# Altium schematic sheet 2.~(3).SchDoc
size 420 x 297 mm
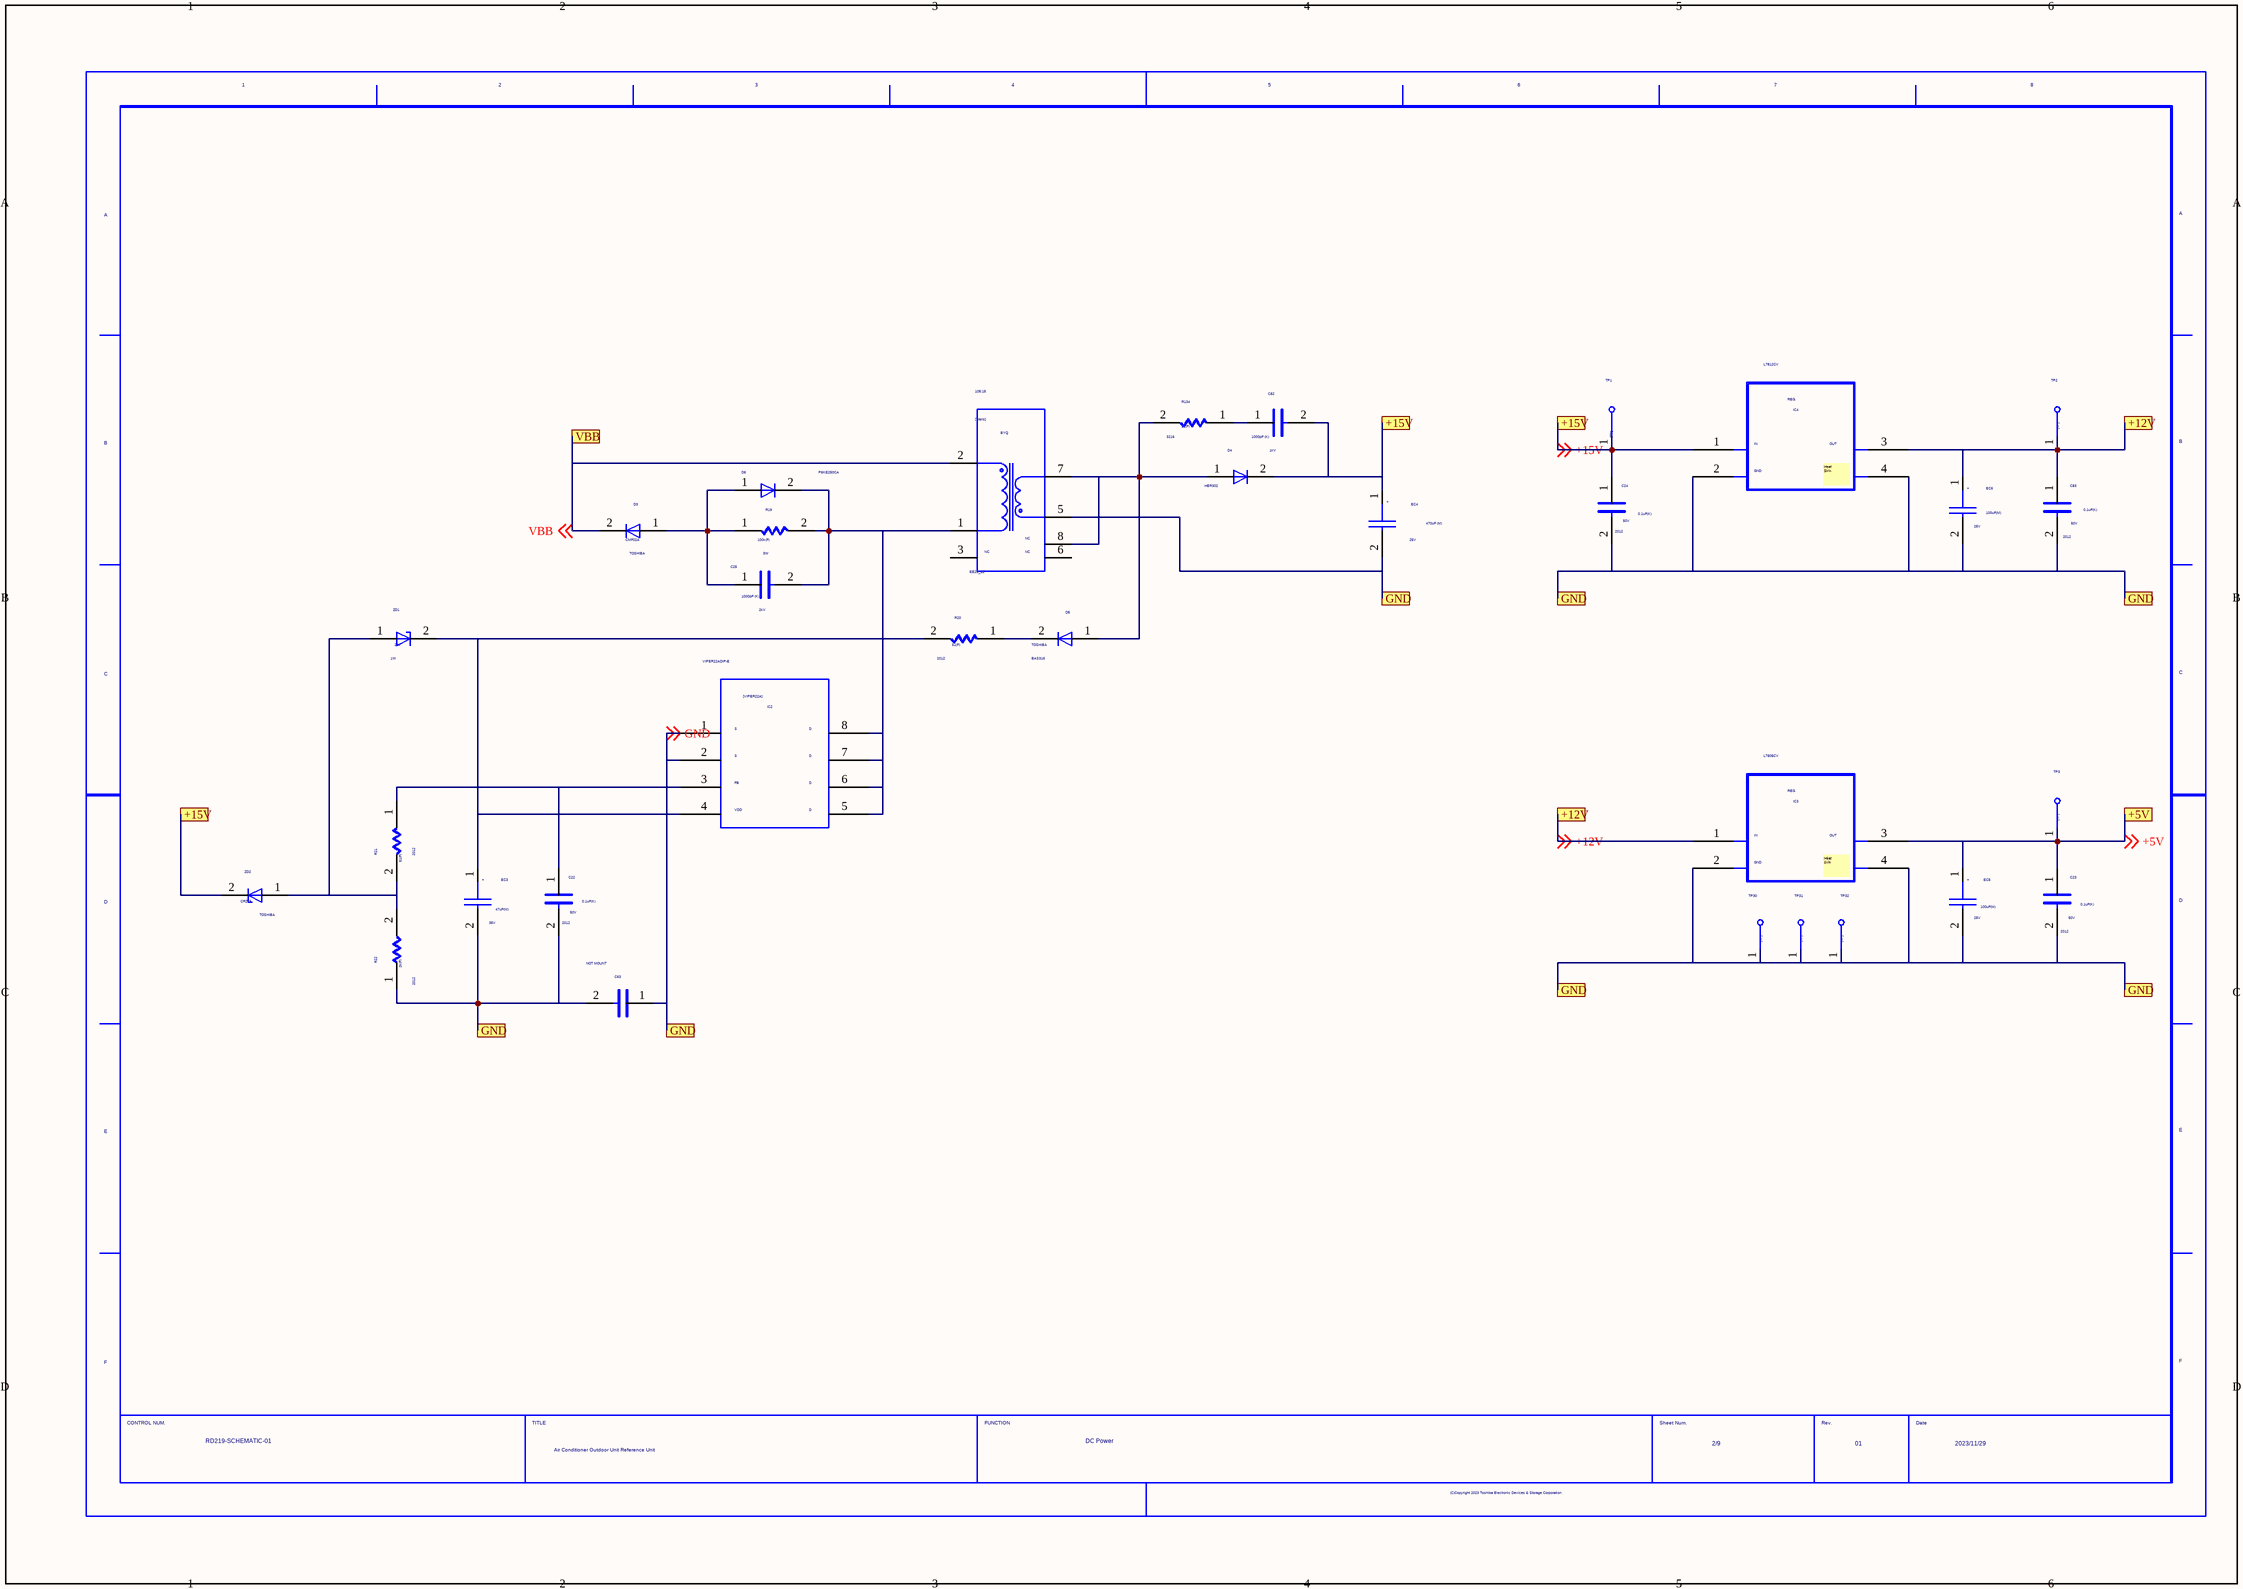
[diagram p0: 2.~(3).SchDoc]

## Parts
BYQ  VAL3: EE25_22  VAL1: 105:15  (hidden comment: EE25-22)
C22  SIZECODESMD: 2012  VAL2: 50V  VAL1: 0.1uF(K)  (hidden comment: C)
C23  SIZECODESMD: 2012  VAL2: 50V  VAL1: 0.1uF(K)  (hidden comment: C)
C24  SIZECODESMD: 2012  VAL2: 50V  VAL1: 0.1uF(K)  (hidden comment: C)
C25  VAL2: 2kV  VAL1: 1000pF (K)  (hidden comment: C)
C63  NOTMOUNT: NOT MOUNT  (hidden comment: C)
C82  VAL2: 1kV  VAL1: 1000pF (K)  (hidden comment: C)
C83  SIZECODESMD: 2012  VAL2: 50V  VAL1: 0.1uF(K)  (hidden comment: C)
D3  USERCOMPTEXT3: TOSHIBA  VAL3: CMF02A  (hidden comment: D_CUSTOM)
D4  VAL3: HER302  (hidden comment: D_CUSTOM)
D5  USERCOMPTEXT3: TOSHIBA  VAL3: BAS316  (hidden comment: D_CUSTOM)
D6  VAL3: P6KE250CA  (hidden comment: D_CUSTOM)
EC3  VAL2: 35V  VAL1: 47uF(M)  (hidden comment: EC)
EC4  VAL2: 25V  VAL1: 470uF (M)  (hidden comment: EC)
EC5  VAL2: 25V  VAL1: 100uF(M)  (hidden comment: EC)
EC6  VAL2: 25V  VAL1: 100uF(M)  (hidden comment: EC)
IC2  VAL1: VIPER22ADIP-E  (hidden comment: VIPER22A)
IC3  VAL3: L7805CV  (hidden comment: REG)
IC4  VAL3: L7812CV  (hidden comment: REG)
R19  VAL2: 3W  VAL1: 100k(F)  (hidden comment: R)
R20  SIZECODESMD: 2012  VAL1: 51(F)  (hidden comment: R)
R21  SIZECODESMD: 2012  VAL1: 51(F)  (hidden comment: R)
R22  SIZECODESMD: 2012  VAL1: 2k(F)  (hidden comment: R)
R134  SIZECODESMD: 3216  VAL1: 22(F)  (hidden comment: R)
TP1  TP  (value not drawn)
TP2  TP  (value not drawn)
TP3  TP  (value not drawn)
TP30  TP  (value not drawn)
TP31  TP  (value not drawn)
TP32  TP  (value not drawn)
U?  DATE: 2023/11/29  TITLE: Air Conditioner Outdoor Unit / Reference Unit  SHEETNUMBER: 2/9  FUNCTION: DC Power  REVISION: 01  DRAWINGNUMBER: RD219-SCHEMATIC-01  (hidden comment: WAKU_DEF100)
ZD1  VAL2: 1W  VAL1: 24V  (hidden comment: ZD)
ZD2  USERCOMPTEXT3: TOSHIBA  VAL1: CRZ15  (hidden comment: ZD)

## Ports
+5V, +12V, +15V, GND, VBB

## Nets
+5V: C23.1 EC5.1 IC3.3 TP3.1 ; off-sheet +5V, port +5V
+12V: C83.1 EC6.1 IC3.1 IC4.3 TP2.1 ; off-sheet +12V, port +12V
+15V: C24.1 C82.2 D4.2 EC4.1 IC4.1 TP1.1 ZD2.2(C) ; off-sheet +15V, port +15V
GND: BYQ.5 C22.2 C23.2 C24.2 C63.1 C63.2 C83.2 EC3.2 EC4.2 EC5.2 EC6.2 IC2.1 IC2.2 IC3.2 IC3.4 IC4.2 IC4.4 R22.1 TP30.1 TP31.1 TP32.1 ; off-sheet GND, port GND
NetBYQ_1: BYQ.1 C25.2 D6.2 IC2.5 IC2.6 IC2.7 IC2.8 R19.2
NetBYQ_7: BYQ.7 BYQ.8 D4.1 D5.1 R134.2
NetC22_1: C22.1 IC2.3 R21.1
NetC25_1: C25.1 D3.1 D6.1 R19.1
NetC82_1: C82.1 R134.1
NetD5_2: D5.2 R20.1
NetEC3_1: EC3.1 IC2.4 R20.2 ZD1.2(C)
NetR21_2: R21.2 R22.2 ZD1.1(A) ZD2.1(A)
VBB: BYQ.2 D3.2 ; off-sheet VBB, port VBB

Not connected (* = marked no-connect by the designer): BYQ 3 6

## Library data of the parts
BYQ = EE25-22: TIME: 15:54:32; UPDATEUSER: w20165dm; UPDATETIME: 16:30:52; SAVECOUNT: 7; SAVEAREA0: -19178,-336,41553,33915; OriginalSymbolOrigin: (5080,30480)
C22-C24 C83 = C: OriginalSymbolOrigin: (2540,7620); VAL3: AC0805KRX7R9BB104
C25 = C: OriginalSymbolOrigin: (2540,7620); VAL3: CK45-B3DD102KYNNA; COMP: 102_2KV
C63 = C: OriginalSymbolOrigin: (2540,7620); COMP: C7.5MM
C82 = C: OriginalSymbolOrigin: (2540,7620); VAL3: CK45-B3AD102KYVNA; COMP: 102_1KV
D3-D6 = D_CUSTOM: SAVEAREA0: -1668,-97,14265,7829; SAVECOUNT: 4; TIME: 14:49:55; UPDATEUSER: w20165dm; UPDATETIME: 16:47:49; OriginalSymbolOrigin: (5080,5080)
EC3 = EC: SAVEAREA0: -1432,-1528,20311,14389; SAVECOUNT: 53; TIME: 15:02:55; UPDATEUSER: w20165dm; UPDATETIME: 16:35:05; OriginalSymbolOrigin: (2540,10160); VAL3: ESY476M035AE3AA; COMP: 35V47uF_6.3X7
EC4 = EC: SAVEAREA0: -1432,-1528,20311,14389; SAVECOUNT: 53; TIME: 15:02:55; UPDATEUSER: w20165dm; UPDATETIME: 16:35:05; OriginalSymbolOrigin: (2540,10160); VAL3: ESH477M025AG4AA
EC5 EC6 = EC: SAVEAREA0: -1432,-1528,20311,14389; SAVECOUNT: 53; TIME: 15:02:55; UPDATEUSER: w20165dm; UPDATETIME: 16:35:05; OriginalSymbolOrigin: (2540,10160); VAL3: ESK107M025AE3AA; COMP: 25V100uF_6.3X11
IC2 = VIPER22A: SAVEAREA0: -16087,-375,51758,33378; SAVECOUNT: 16; TIME: 11:13:15; UPDATEUSER: w20165dm; UPDATETIME: 13:40:21; OriginalSymbolOrigin: (7620,30480); COMP: VIPER22ADIP_E
IC3 IC4 = REG: SAVEAREA0: -5753,-289,46434,25674; SAVECOUNT: 4; TIME: 17:36:06; UPDATEUSER: w20165dm; UPDATETIME: 17:45:44; OriginalSymbolOrigin: (7620,22860)
R19 = R: OriginalSymbolOrigin: (5080,5080); VAL3: MF3WS-100KOhm; COMP: MF3WS_100K
R20 R21 = R: OriginalSymbolOrigin: (5080,5080); VAL3: AC0805FR-0751RL; VAL2: 125mW; COMP: AC0805FR_0751RL
R22 = R: OriginalSymbolOrigin: (5080,5080); VAL2: 125mW; VAL3: AC0805FR-072KL; COMP: AC0805FR_072KL
R134 = R: OriginalSymbolOrigin: (5080,5080); VAL2: 250mW; VAL3: AC1206FR_0722RL
TP1 = TP_Dup1: TIME: 16:12:21; UPDATEUSER: fukuda-y; UPDATETIME: 16:18:11; SAVECOUNT: 2; SAVEAREA0: -242,-92,12810,7836; OriginalSymbolOrigin: (0,7620); VAL3: ZXD; COMPCOMMENT: +15V
TP2 = TP_Dup1: TIME: 16:12:21; UPDATEUSER: fukuda-y; UPDATETIME: 16:18:11; SAVECOUNT: 2; SAVEAREA0: -242,-92,12810,7836; OriginalSymbolOrigin: (0,7620); VAL3: ZXD; COMPCOMMENT: +12V
TP3 = TP_Dup1: TIME: 16:12:21; UPDATEUSER: fukuda-y; UPDATETIME: 16:18:11; SAVECOUNT: 2; SAVEAREA0: -242,-92,12810,7836; OriginalSymbolOrigin: (0,7620); VAL3: ZXD; COMPCOMMENT: +5V
TP30-TP32 = TP_Dup1: TIME: 16:12:21; UPDATEUSER: fukuda-y; UPDATETIME: 16:18:11; SAVECOUNT: 2; SAVEAREA0: -242,-92,12810,7836; OriginalSymbolOrigin: (0,7620); VAL3: ZXD; COMPCOMMENT: GND
U? = WAKU_DEF100: PLOTTIME: HH:MM; SAVEAREA0: -45080,-4508,463680,304612; TIME: 17:44:02; UPDATEUSER: sptcae13; UPDATETIME: 08:19:30; SAVECOUNT: 8; OriginalSymbolOrigin: (10160,284480)
ZD1 = ZD: SAVEAREA0: -4071,-115,16804,10270; TIME: 09:43:08; UPDATEUSER: w20165dm; UPDATETIME: 16:32:57; SAVECOUNT: 6; OriginalSymbolOrigin: (5080,5080); VAL3: ZM4749A
ZD2 = ZD: SAVEAREA0: -4071,-115,16804,10270; TIME: 09:43:08; UPDATEUSER: w20165dm; UPDATETIME: 16:32:57; SAVECOUNT: 6; OriginalSymbolOrigin: (5080,5080)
